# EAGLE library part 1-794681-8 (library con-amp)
Micro MATE-N-LOK Connectors grid 1.5mm Dual Row Through Hole Vertical Metal Through Hole Holddowns Source: ENG_CD_794681_E.pdf
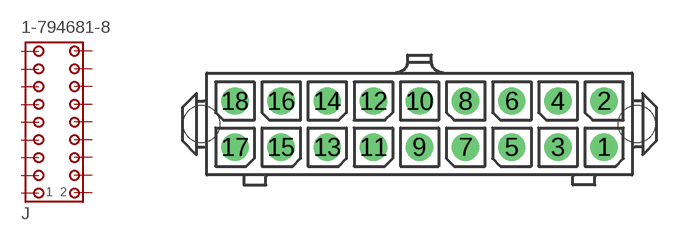
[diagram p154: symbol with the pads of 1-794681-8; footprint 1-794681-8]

Designator prefix J

## 1-794681-8 (MF: TYCO ELECTRONICS; MPN: 1-794681-8; OC_FARNELL: unknown; OC_NEWARK: 10H3813)  [1-794681-8]
1  1  pas
2  2  pas
3  3  pas
4  4  pas
5  5  pas
6  6  pas
7  7  pas
8  8  pas
9  9  pas
10  10  pas
11  11  pas
12  12  pas
13  13  pas
14  14  pas
15  15  pas
16  16  pas
17  17  pas
18  18  pas

## Footprint 1-794681-8 (pad centres in mm)
Micro MATE-N-LOK Connectors grid 1.5mm Dual Row Through Hole Vertical Metal Through Hole Holddowns Source: ENG_CD_794681_E.pdf
drill 1 pad 1.778 round: 1 12,-1.5; 2 12,1.5; 3 9,-1.5; 4 9,1.5; 5 6,-1.5; 6 6,1.5; 7 3,-1.5; 8 3,1.5; 9 0,-1.5; 10 0,1.5; 11 -3,-1.5; 12 -3,1.5; 13 -6,-1.5; 14 -6,1.5; 15 -9,-1.5; 16 -9,1.5; 17 -12,-1.5; 18 -12,1.5
hole 2.4 at 14.13,0
hole 2.4 at -14.17,0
